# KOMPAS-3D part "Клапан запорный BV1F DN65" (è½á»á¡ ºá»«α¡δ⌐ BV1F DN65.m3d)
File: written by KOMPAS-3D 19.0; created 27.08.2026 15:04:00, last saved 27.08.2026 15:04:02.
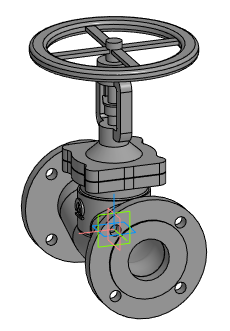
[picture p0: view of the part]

Document properties: Автор: Энергия; Полное имя файла: E:\Dendor\_3D для проектировщиков\5.6 Клапан запорный BV1F\stp\Клапан запорный BV1F DN65.m3d

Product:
- Part/product: Клапан запорный BV1F DN65
    Масса: 25.3825

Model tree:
1. Операция без истории:1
